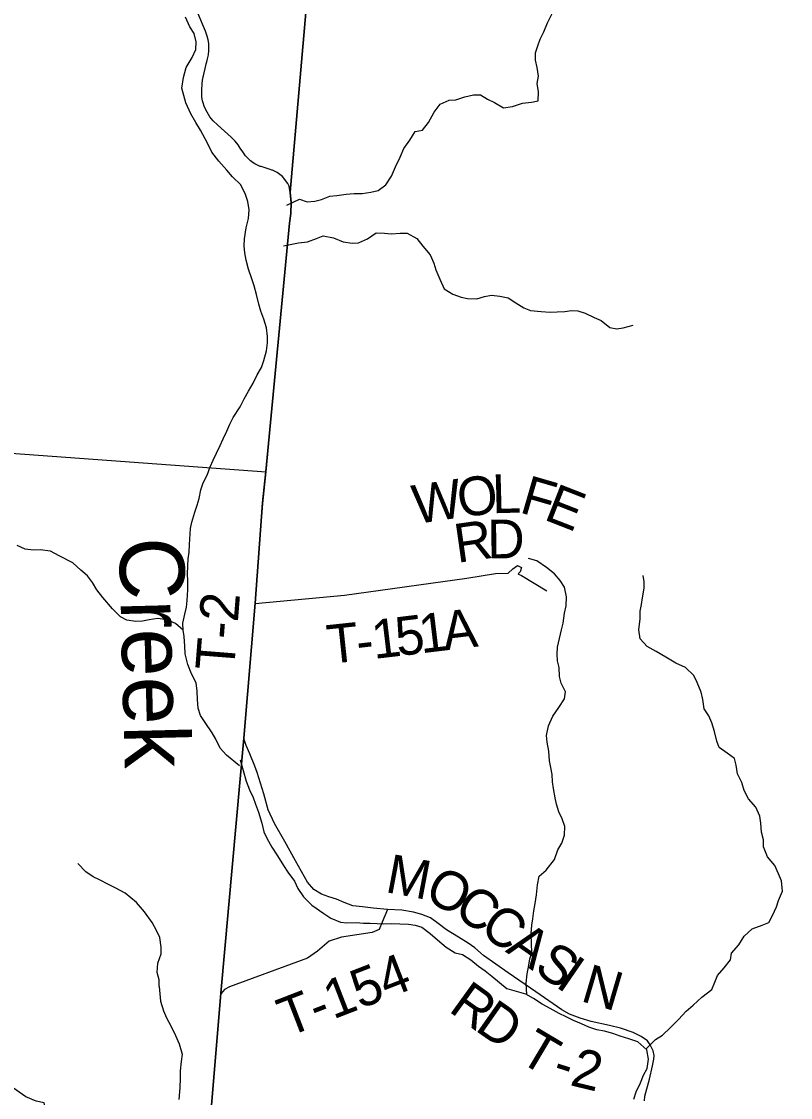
# Model space of a CAD drawing. Extents: x 0 to 42.5, y 0 to 22.
# Drawn here: x 8.111 to 8.674, y 16.629 to 17.417 of the extents above; entities that cross this region are included whole.
import ezdxf

# ---------------------------------------------------------------- set-up
doc = ezdxf.new("R2010")
doc.units = 0
for name, color, linetype in [('GM_X_Interchange_Ramps', 7, 'Continuous'), ('GM_X_Minor_River', 7, 'Continuous'), ('GM_X_Minor_River_Text', 7, 'Continuous'), ('GM_X_Township', 7, 'Continuous'), ('GM_X_Township_Road', 7, 'Continuous'), ('GM_X_Township_Road_Text', 7, 'Continuous'), ('SH_Cut_Line', 7, 'Continuous')]:
    doc.layers.add(name, color=color, linetype=linetype)

msp = doc.modelspace()

# ---------------------------------------------------------------- linework, layer by layer
at = {"layer": 'GM_X_Interchange_Ramps'}
msp.add_lwpolyline([(8.9, 15.53758), (8.9, 19.05381), (8.80207, 19.06082), (8.79715, 19.06117), (8.45529, 19.08562), (8.42249, 18.59682), (8.4216, 18.58362), (8.41233, 18.47844), (8.38323, 18.14846), (8.33786, 17.63394), (8.30797, 17.29222), (8.30866, 17.28459), (8.30841, 17.27648), (8.30737, 17.26941), (8.29023, 17.08765), (8.28773, 17.0646), (8.28228, 16.99116), (8.27401, 16.89234), (8.25723, 16.70556), (8.24802, 16.59431), (8.24781, 16.59008), (8.17933, 15.79111)], dxfattribs=at)
at = {"layer": 'GM_X_Minor_River'}
for p, q in [((8.4965, 17.4162), (8.50014, 17.42359)), ((8.49363, 17.40958), (8.4965, 17.4162)), ((8.49115, 17.40428), (8.49363, 17.40958)), ((8.48769, 17.39424), (8.48923, 17.39935)), ((8.48923, 17.39935), (8.49115, 17.40428)), ((8.48767, 17.38893), (8.48769, 17.39424)), ((8.48879, 17.38342), (8.48767, 17.38893)), ((8.4899, 17.37716), (8.48879, 17.38342)), ((8.48874, 17.37186), (8.4899, 17.37716)), ((8.48986, 17.36559), (8.48874, 17.37186)), ((8.41777, 17.35677), (8.42442, 17.35959)), ((8.42442, 17.35959), (8.42916, 17.35995)), ((8.42916, 17.35995), (8.4358, 17.36201)), ((8.4358, 17.36201), (8.44226, 17.3635)), ((8.44226, 17.3635), (8.44738, 17.36348)), ((8.44738, 17.36348), (8.45248, 17.36024)), ((8.45248, 17.36024), (8.45759, 17.35794)), ((8.47807, 17.35748), (8.48471, 17.35803)), ((8.48471, 17.35803), (8.48964, 17.35915)), ((8.48964, 17.35915), (8.48986, 17.36559)), ((8.40937, 17.34333), (8.41339, 17.35072)), ((8.41339, 17.35072), (8.41777, 17.35677)), ((8.45759, 17.35794), (8.46421, 17.35393)), ((8.46421, 17.35393), (8.47085, 17.35486)), ((8.47085, 17.35486), (8.47807, 17.35748)), ((8.4048, 17.33766), (8.40937, 17.34333)), ((8.39548, 17.3303), (8.39949, 17.33655)), ((8.39949, 17.33655), (8.4048, 17.33766)), ((8.39129, 17.32425), (8.39548, 17.3303)), ((8.38861, 17.31781), (8.39129, 17.32425)), ((8.38229, 17.30399), (8.38516, 17.31081)), ((8.38516, 17.31081), (8.38861, 17.31781)), ((8.3781, 17.29756), (8.38229, 17.30399)), ((8.37239, 17.29341), (8.3781, 17.29756)), ((8.33103, 17.28674), (8.33711, 17.28919)), ((8.33711, 17.28919), (8.34223, 17.28973)), ((8.34223, 17.28973), (8.34887, 17.29085)), ((8.34887, 17.29085), (8.35494, 17.2912)), ((8.35494, 17.2912), (8.36063, 17.29118)), ((8.36063, 17.29118), (8.36708, 17.2921)), ((8.36708, 17.2921), (8.37239, 17.29341)), ((8.30553, 17.28259), (8.31492, 17.287)), ((8.31492, 17.287), (8.32041, 17.28508)), ((8.32041, 17.28508), (8.3261, 17.28562)), ((8.3261, 17.28562), (8.33103, 17.28674)), ((8.31403, 17.25514), (8.32067, 17.25587)), ((8.32067, 17.25587), (8.32731, 17.25831)), ((8.32731, 17.25831), (8.33206, 17.26019)), ((8.33206, 17.26019), (8.33964, 17.25883)), ((8.33964, 17.25883), (8.34683, 17.25596)), ((8.34683, 17.25596), (8.35328, 17.2548)), ((8.35802, 17.25516), (8.36448, 17.25798)), ((8.36448, 17.25798), (8.37094, 17.26232)), ((8.37094, 17.26232), (8.37701, 17.2621)), ((8.37701, 17.2621), (8.38193, 17.2617)), ((8.38193, 17.2617), (8.38857, 17.26225)), ((8.38857, 17.26225), (8.39369, 17.26223)), ((8.39369, 17.26223), (8.40069, 17.25822)), ((8.40069, 17.25822), (8.40522, 17.2527)), ((8.30303, 17.25298), (8.31403, 17.25514)), ((8.35328, 17.2548), (8.35802, 17.25516)), ((8.40522, 17.2527), (8.4105, 17.24623)), ((8.4105, 17.24623), (8.41313, 17.24034)), ((8.41313, 17.24034), (8.41463, 17.23541)), ((8.41463, 17.23541), (8.41745, 17.22857)), ((8.41745, 17.22857), (8.42083, 17.22154)), ((8.42083, 17.22154), (8.42707, 17.21753)), ((8.42707, 17.21753), (8.43313, 17.21523)), ((8.4502, 17.21574), (8.45532, 17.21667)), ((8.45532, 17.21667), (8.46139, 17.21607)), ((8.43313, 17.21523), (8.43787, 17.21427)), ((8.43787, 17.21427), (8.44469, 17.21405)), ((8.44469, 17.21405), (8.4502, 17.21574)), ((8.46139, 17.21607), (8.46764, 17.21491)), ((8.46764, 17.21491), (8.47331, 17.21129)), ((8.47331, 17.21129), (8.47899, 17.20747)), ((8.47899, 17.20747), (8.48391, 17.20556)), ((8.48391, 17.20556), (8.49168, 17.20477)), ((8.49168, 17.20477), (8.49831, 17.20436)), ((8.49831, 17.20436), (8.50343, 17.20453)), ((8.50343, 17.20453), (8.50912, 17.20489)), ((8.50912, 17.20489), (8.51386, 17.20544)), ((8.51386, 17.20544), (8.5186, 17.20542)), ((8.5186, 17.20542), (8.52391, 17.20351)), ((8.52391, 17.20351), (8.53053, 17.20045)), ((8.53053, 17.20045), (8.53564, 17.19834)), ((8.53564, 17.19834), (8.54207, 17.1932)), ((8.54207, 17.1932), (8.54718, 17.19204)), ((8.54718, 17.19204), (8.55193, 17.19297)), ((8.55193, 17.19297), (8.55914, 17.19484)), ((8.48867, 17.02215), (8.48261, 17.02407)), ((8.49567, 17.01738), (8.48867, 17.02215)), ((8.50153, 17.01281), (8.49567, 17.01738)), ((8.50568, 17.00786), (8.50153, 17.01281)), ((8.5673, 17.00687), (8.56656, 17.01161)), ((8.50888, 17.00292), (8.50568, 17.00786)), ((8.56709, 17.00213), (8.5673, 17.00687)), ((8.51037, 16.9959), (8.50888, 17.00292)), ((8.50997, 16.98926), (8.51037, 16.9959)), ((8.56592, 16.99511), (8.56709, 17.00213)), ((8.50881, 16.98396), (8.50997, 16.98926)), ((8.56437, 16.98545), (8.56534, 16.99038)), ((8.56534, 16.99038), (8.56592, 16.99511)), ((8.50783, 16.97656), (8.50881, 16.98396)), ((8.56416, 16.97976), (8.56437, 16.98545)), ((8.50667, 16.97183), (8.50783, 16.97656)), ((8.56336, 16.97161), (8.56416, 16.97976)), ((8.50378, 16.95913), (8.50513, 16.96538)), ((8.50513, 16.96538), (8.50667, 16.97183)), ((8.56429, 16.96516), (8.56336, 16.97161)), ((8.56938, 16.95945), (8.56429, 16.96516)), ((8.50338, 16.95382), (8.50378, 16.95913)), ((8.576, 16.95582), (8.56938, 16.95945)), ((8.50374, 16.94908), (8.50338, 16.95382)), ((8.50486, 16.94414), (8.50374, 16.94908)), ((8.583, 16.95162), (8.576, 16.95582)), ((8.59038, 16.94723), (8.583, 16.95162)), ((8.50521, 16.93751), (8.50486, 16.94414)), ((8.59738, 16.94417), (8.59038, 16.94723)), ((8.60362, 16.93826), (8.59738, 16.94417)), ((8.50652, 16.93276), (8.50521, 16.93751)), ((8.50953, 16.9263), (8.50652, 16.93276)), ((8.60606, 16.93314), (8.60362, 16.93826)), ((8.60888, 16.92611), (8.60606, 16.93314)), ((8.50875, 16.92118), (8.50953, 16.9263)), ((8.61018, 16.9206), (8.60888, 16.92611)), ((8.50474, 16.91494), (8.50875, 16.92118)), ((8.6111, 16.91396), (8.61018, 16.9206)), ((8.50035, 16.90851), (8.50474, 16.91494)), ((8.6145, 16.90864), (8.6111, 16.91396)), ((8.49575, 16.8943), (8.4971, 16.90132)), ((8.4971, 16.90132), (8.50035, 16.90851)), ((8.61675, 16.90351), (8.6145, 16.90864)), ((8.61881, 16.89724), (8.61675, 16.90351)), ((8.49611, 16.88937), (8.49575, 16.8943)), ((8.6203, 16.89022), (8.61881, 16.89724)), ((8.49741, 16.88292), (8.49611, 16.88937)), ((8.62199, 16.88547), (8.6203, 16.89022)), ((8.62785, 16.88147), (8.62199, 16.88547)), ((8.49795, 16.8759), (8.49741, 16.88292)), ((8.63333, 16.87746), (8.62785, 16.88147)), ((8.63445, 16.87272), (8.63333, 16.87746)), ((8.27124, 16.87644), (8.27567, 16.86082)), ((8.49888, 16.87096), (8.49795, 16.8759)), ((8.4998, 16.86584), (8.49888, 16.87096)), ((8.63556, 16.86627), (8.63445, 16.87272)), ((8.50016, 16.86034), (8.4998, 16.86584)), ((8.63876, 16.85981), (8.63556, 16.86627)), ((8.27567, 16.86082), (8.2783, 16.85456)), ((8.2783, 16.85456), (8.28093, 16.84886)), ((8.5009, 16.85541), (8.50016, 16.86034)), ((8.50201, 16.84876), (8.5009, 16.85541)), ((8.64044, 16.85411), (8.63876, 16.85981)), ((8.64364, 16.84784), (8.64044, 16.85411)), ((8.28093, 16.84886), (8.28262, 16.84411)), ((8.50294, 16.84402), (8.50201, 16.84876)), ((8.64893, 16.84194), (8.64364, 16.84784)), ((8.28262, 16.84411), (8.28487, 16.83822)), ((8.28487, 16.83822), (8.28711, 16.83025)), ((8.50481, 16.83832), (8.50294, 16.84402)), ((8.50707, 16.83319), (8.50481, 16.83832)), ((8.65193, 16.83529), (8.64893, 16.84194)), ((8.28711, 16.83025), (8.28861, 16.82379)), ((8.50913, 16.82769), (8.50707, 16.83319)), ((8.65267, 16.83017), (8.65193, 16.83529)), ((8.65303, 16.82353), (8.65267, 16.83017)), ((8.28861, 16.82379), (8.29086, 16.81904)), ((8.50892, 16.82143), (8.50913, 16.82769)), ((8.65452, 16.81783), (8.65303, 16.82353)), ((8.29086, 16.81904), (8.29463, 16.81258)), ((8.50394, 16.81064), (8.507, 16.81556)), ((8.507, 16.81556), (8.50892, 16.82143)), ((8.6545, 16.81271), (8.65452, 16.81783)), ((8.29463, 16.81258), (8.29858, 16.80631)), ((8.50145, 16.80344), (8.50394, 16.81064)), ((8.6575, 16.8055), (8.6545, 16.81271)), ((8.29858, 16.80631), (8.30311, 16.79908)), ((8.30311, 16.79908), (8.30631, 16.79433)), ((8.49554, 16.79569), (8.50145, 16.80344)), ((8.66279, 16.79922), (8.6575, 16.8055)), ((8.66561, 16.79295), (8.66279, 16.79922)), ((8.30631, 16.79433), (8.31121, 16.78767)), ((8.48905, 16.7849), (8.49021, 16.79135)), ((8.49021, 16.79135), (8.49554, 16.79569)), ((8.66786, 16.78782), (8.66561, 16.79295)), ((8.31121, 16.78767), (8.31366, 16.78235)), ((8.48845, 16.7777), (8.48905, 16.7849)), ((8.6684, 16.78042), (8.66786, 16.78782)), ((8.31366, 16.78235), (8.3178, 16.77608)), ((8.3178, 16.77608), (8.32385, 16.76999)), ((8.48748, 16.77126), (8.48845, 16.7777)), ((8.66553, 16.7736), (8.6684, 16.78042)), ((8.32385, 16.76999), (8.33273, 16.76389)), ((8.48651, 16.76595), (8.48748, 16.77126)), ((8.66112, 16.76243), (8.66399, 16.76887)), ((8.66399, 16.76887), (8.66553, 16.7736)), ((8.33273, 16.76389), (8.33784, 16.76064)), ((8.33784, 16.76064), (8.34484, 16.75758)), ((8.48495, 16.75533), (8.48573, 16.76007)), ((8.48573, 16.76007), (8.48651, 16.76595)), ((8.65845, 16.75751), (8.66112, 16.76243)), ((8.34484, 16.75758), (8.34958, 16.75718)), ((8.34958, 16.75718), (8.35622, 16.75735)), ((8.35622, 16.75735), (8.36171, 16.75695)), ((8.36171, 16.75695), (8.36664, 16.75693)), ((8.36664, 16.75693), (8.37176, 16.75672)), ((8.37176, 16.75672), (8.3765, 16.75651)), ((8.3765, 16.75651), (8.382, 16.75668)), ((8.382, 16.75668), (8.38826, 16.75646)), ((8.38826, 16.75646), (8.3947, 16.75625)), ((8.3947, 16.75625), (8.39944, 16.75547)), ((8.39944, 16.75547), (8.40436, 16.75394)), ((8.40436, 16.75394), (8.41041, 16.74936)), ((8.48455, 16.74927), (8.48495, 16.75533)), ((8.6404, 16.74734), (8.6463, 16.75282)), ((8.6463, 16.75282), (8.65351, 16.75545)), ((8.65351, 16.75545), (8.65845, 16.75751)), ((8.41041, 16.74936), (8.41589, 16.7446)), ((8.41589, 16.7446), (8.42232, 16.73927)), ((8.48471, 16.74187), (8.48455, 16.74927)), ((8.63658, 16.7411), (8.6404, 16.74734)), ((8.42232, 16.73927), (8.42875, 16.73526)), ((8.48487, 16.73542), (8.48471, 16.74187)), ((8.63106, 16.73486), (8.63658, 16.7411)), ((8.42875, 16.73526), (8.43405, 16.73391)), ((8.43405, 16.73391), (8.44029, 16.73009)), ((8.44029, 16.73009), (8.44577, 16.72533)), ((8.48255, 16.72462), (8.48353, 16.73069)), ((8.48353, 16.73069), (8.48487, 16.73542)), ((8.62589, 16.72426), (8.63047, 16.73012)), ((8.63047, 16.73012), (8.63106, 16.73486)), ((8.44577, 16.72533), (8.45069, 16.7219)), ((8.45069, 16.7219), (8.4556, 16.71809)), ((8.48159, 16.71969), (8.48255, 16.72462)), ((8.62094, 16.71859), (8.62589, 16.72426)), ((8.4556, 16.71809), (8.46694, 16.70876)), ((8.4808, 16.71287), (8.48159, 16.71969)), ((8.48124, 16.70463), (8.4808, 16.71287)), ((8.61673, 16.70845), (8.61903, 16.71367)), ((8.61903, 16.71367), (8.62094, 16.71859)), ((8.48053, 16.70503), (8.46694, 16.70876)), ((8.48619, 16.70177), (8.48053, 16.70503)), ((8.60946, 16.70268), (8.61673, 16.70845)), ((8.4926, 16.69756), (8.48619, 16.70177)), ((8.49825, 16.6943), (8.4926, 16.69756)), ((8.59784, 16.69252), (8.60317, 16.69684)), ((8.60317, 16.69684), (8.60946, 16.70268)), ((8.50486, 16.69084), (8.49825, 16.6943)), ((8.50995, 16.68834), (8.50486, 16.69084)), ((8.51542, 16.68565), (8.50995, 16.68834)), ((8.5923, 16.68629), (8.59784, 16.69252)), ((8.52127, 16.68315), (8.51542, 16.68565)), ((8.52656, 16.68065), (8.52127, 16.68315)), ((8.53241, 16.67891), (8.52656, 16.68065)), ((8.58067, 16.67499), (8.58658, 16.68045)), ((8.58658, 16.68045), (8.5923, 16.68629)), ((8.53809, 16.67792), (8.53241, 16.67891)), ((8.54413, 16.67599), (8.53809, 16.67792)), ((8.54961, 16.67424), (8.54413, 16.67599)), ((8.55603, 16.67231), (8.54961, 16.67424)), ((8.57553, 16.67161), (8.58067, 16.67499)), ((8.56265, 16.66999), (8.55603, 16.67231)), ((8.56904, 16.66407), (8.56265, 16.66999)), ((8.56831, 16.66475), (8.57553, 16.67161)), ((8.57032, 16.65723), (8.56904, 16.66407)), ((8.56932, 16.65041), (8.57032, 16.65723)), ((8.56682, 16.6455), (8.56932, 16.65041)), ((8.56451, 16.64001), (8.56682, 16.6455)), ((8.5595, 16.62791), (8.56143, 16.63339)), ((8.56143, 16.63339), (8.56451, 16.64001))]:
    msp.add_line(p, q, dxfattribs=at)
for points in [[(8.27093, 16.87219), (8.26134, 16.88001), (8.25661, 16.88514), (8.25359, 16.8916), (8.25094, 16.89634), (8.24564, 16.90394), (8.24223, 16.90889), (8.24054, 16.91439), (8.24017, 16.92065), (8.2398, 16.92673), (8.23924, 16.9328), (8.23565, 16.93945), (8.233, 16.94628), (8.23112, 16.95426), (8.23075, 16.95976), (8.23039, 16.96678), (8.22964, 16.97153), (8.22927, 16.97665), (8.23079, 16.98329), (8.23194, 16.98841), (8.23252, 16.99316), (8.23291, 17.00112), (8.23293, 17.00776), (8.23274, 17.01251), (8.23294, 17.01858), (8.23333, 17.0237), (8.23391, 17.02864), (8.2343, 17.03414), (8.23508, 17.0459), (8.23604, 17.05064), (8.23814, 17.05785), (8.23985, 17.06297), (8.24138, 17.0679), (8.24253, 17.07435), (8.24425, 17.07928), (8.24729, 17.08497), (8.24939, 17.09103), (8.25168, 17.09596), (8.25396, 17.10108), (8.25663, 17.10658), (8.25891, 17.11151), (8.26158, 17.1172), (8.26368, 17.12231), (8.26615, 17.12724), (8.27129, 17.13501), (8.27433, 17.14089), (8.27738, 17.14639), (8.2808, 17.15245), (8.28385, 17.15833), (8.28708, 17.16382), (8.28861, 17.16894), (8.29052, 17.17596), (8.29148, 17.18184), (8.2913, 17.18659), (8.29055, 17.19285), (8.28867, 17.1993), (8.28659, 17.20519), (8.28508, 17.21013), (8.2832, 17.21734), (8.28169, 17.22361), (8.2798, 17.22873), (8.27754, 17.23576), (8.27565, 17.2424), (8.27471, 17.24772), (8.27416, 17.25303), (8.27454, 17.25816), (8.2757, 17.26612), (8.27742, 17.27295), (8.278, 17.2794), (8.27687, 17.28529), (8.27536, 17.2906), (8.27177, 17.29763), (8.26571, 17.30352), (8.26154, 17.30828), (8.25567, 17.31493), (8.25056, 17.32139), (8.2483, 17.32614), (8.24565, 17.33127), (8.24225, 17.33754), (8.23884, 17.34324), (8.23525, 17.34969), (8.23166, 17.35767), (8.22864, 17.3683), (8.22979, 17.37627), (8.23189, 17.38348), (8.23627, 17.39087), (8.23894, 17.39675), (8.23914, 17.40225), (8.23763, 17.40832), (8.23441, 17.41326), (8.23139, 17.42029)], [(8.22964, 16.97153), (8.22395, 16.97628), (8.21789, 16.97914), (8.21106, 16.97991), (8.20461, 16.97898), (8.19986, 16.97804), (8.19493, 16.97786), (8.18848, 16.97882), (8.18374, 16.9813), (8.17787, 16.987), (8.17087, 16.99536), (8.16651, 17.00106), (8.16311, 17.00638), (8.15951, 17.01114), (8.15478, 17.01532), (8.14872, 17.02083), (8.13886, 17.02579), (8.13242, 17.02921), (8.12483, 17.03037), (8.12009, 17.03), (8.11402, 17.03077), (8.10795, 17.03344)], [(8.21209, 16.71046), (8.2121, 16.7154), (8.21059, 16.72071), (8.21117, 16.72773), (8.21346, 16.73437), (8.21347, 16.7393), (8.21253, 16.74652), (8.21008, 16.75164), (8.20686, 16.75734), (8.20138, 16.76532), (8.19532, 16.77198), (8.18717, 16.77882), (8.18035, 16.78244), (8.17485, 16.78511), (8.16841, 16.78854), (8.16367, 16.79082), (8.15836, 16.79444), (8.15249, 16.80052)], [(8.21209, 16.71046), (8.21295, 16.69987), (8.21517, 16.69264), (8.21741, 16.68751), (8.22078, 16.68122), (8.22396, 16.67475), (8.22657, 16.66866), (8.22879, 16.66105), (8.22818, 16.65555), (8.22738, 16.64873), (8.22734, 16.64341), (8.2271, 16.63639), (8.22648, 16.62786)], [(8.11071, 16.57261), (8.11623, 16.57656), (8.1214, 16.58317), (8.12427, 16.58808), (8.12621, 16.59396), (8.12757, 16.59983), (8.12875, 16.60627), (8.12959, 16.6169), (8.12794, 16.62545), (8.12188, 16.62662), (8.11433, 16.62971), (8.10282, 16.63775)]]:
    msp.add_lwpolyline(points, dxfattribs=at)
at = {"layer": 'GM_X_Township'}
msp.add_lwpolyline([(8.33786, 17.63394), (8.30797, 17.29222), (8.30866, 17.28459), (8.30841, 17.27648), (8.30737, 17.26941), (8.29023, 17.08765), (8.28773, 17.0646), (8.28228, 16.99116), (8.27401, 16.89234), (8.25723, 16.70556), (8.24802, 16.59431), (8.24781, 16.59008), (8.17933, 15.79111)], dxfattribs=at)
at = {"layer": 'GM_X_Township_Road'}
for p, q in [((7.44962, 17.14878), (8.29034, 17.08739)), ((8.27412, 16.89208), (8.28239, 16.9909))]:
    msp.add_line(p, q, dxfattribs=at)
for points in [[(8.30808, 17.29196), (8.3072, 17.29658), (8.30617, 17.29846), (8.30237, 17.30364), (8.29839, 17.30659), (8.29646, 17.3076), (8.29504, 17.30821), (8.29446, 17.30843), (8.29333, 17.30891), (8.29045, 17.3097), (8.28665, 17.31095), (8.28607, 17.31112), (8.28409, 17.31196), (8.28219, 17.31295), (8.28091, 17.31377), (8.27899, 17.31526), (8.27718, 17.31689), (8.27531, 17.31893), (8.27332, 17.32167), (8.27143, 17.32451), (8.26984, 17.32681), (8.26771, 17.32947), (8.26468, 17.33258), (8.25983, 17.33694), (8.25472, 17.34147), (8.25163, 17.34451), (8.24923, 17.34734), (8.24806, 17.34917), (8.24629, 17.35244), (8.24508, 17.3553), (8.24423, 17.35763), (8.24384, 17.35913), (8.24339, 17.36188), (8.24328, 17.36435), (8.24335, 17.36714), (8.24358, 17.37149), (8.24384, 17.37427), (8.24425, 17.37674), (8.24443, 17.37734), (8.24625, 17.38488), (8.24651, 17.38609), (8.24673, 17.38698), (8.24699, 17.38777), (8.24748, 17.3898), (8.24805, 17.39282), (8.2484, 17.39592), (8.24849, 17.39871), (8.24833, 17.40119), (8.24795, 17.40365), (8.24725, 17.40636), (8.24591, 17.41017), (8.24381, 17.41535), (8.24013, 17.42392)], [(8.29034, 17.08739), (8.30748, 17.26915), (8.30852, 17.27621), (8.30877, 17.28432), (8.30808, 17.29196)], [(8.28239, 16.9909), (8.28784, 17.06434), (8.29034, 17.08739)], [(8.28239, 16.9909), (8.34782, 16.99718), (8.43741, 17.00953), (8.45838, 17.01299), (8.46772, 17.01322), (8.471, 17.01649), (8.47455, 17.01876), (8.47726, 17.01734), (8.4764, 17.01421), (8.47484, 17.01279), (8.47524, 17.01256)], [(8.47524, 17.01256), (8.47727, 17.01144), (8.49599, 17.00017)], [(8.56734, 16.62681), (8.56777, 16.63011), (8.57107, 16.64275), (8.57323, 16.65238), (8.57423, 16.65726), (8.57452, 16.65999), (8.57366, 16.66344), (8.57165, 16.6679), (8.56963, 16.67062), (8.56489, 16.67393), (8.55915, 16.67695), (8.54981, 16.68011), (8.54176, 16.68197), (8.5284, 16.68499), (8.52021, 16.68729), (8.5126, 16.69031), (8.507, 16.69347), (8.48775, 16.70668), (8.46763, 16.72062), (8.44953, 16.73312), (8.44321, 16.73887), (8.43833, 16.74217), (8.43129, 16.74677), (8.42238, 16.75194), (8.41635, 16.75668), (8.41074, 16.7607), (8.40428, 16.76329), (8.39824, 16.76487), (8.38962, 16.76645), (8.37914, 16.76688), (8.36874, 16.76798), (8.36087, 16.76881), (8.35393, 16.76954), (8.34753, 16.77205), (8.34193, 16.77449), (8.33633, 16.77607), (8.33101, 16.77823), (8.32526, 16.78153), (8.32067, 16.78699), (8.31636, 16.79475), (8.31176, 16.80265), (8.304, 16.81673), (8.29639, 16.8298), (8.29193, 16.84), (8.28863, 16.8515), (8.28374, 16.86716), (8.28202, 16.8719), (8.27843, 16.8808), (8.27584, 16.88698), (8.27412, 16.89208)], [(8.37914, 16.76688), (8.37543, 16.75766), (8.37308, 16.75218), (8.36811, 16.74996), (8.34544, 16.74662), (8.33647, 16.74369), (8.32802, 16.73638), (8.32054, 16.73134), (8.26352, 16.71034), (8.25986, 16.70823), (8.25734, 16.7053)], [(8.24792, 16.58982), (8.24813, 16.59404), (8.25734, 16.7053)]]:
    msp.add_lwpolyline(points, dxfattribs=at)
at = {"layer": 'SH_Cut_Line'}
for points in [[(8.9, 14.1), (8.9, 19.05381), (8.80207, 19.06082), (8.79715, 19.06117), (8.45529, 19.08562), (8.42249, 18.59682), (8.4216, 18.58362), (8.41233, 18.47844), (8.38323, 18.14846), (8.33786, 17.63394), (8.30797, 17.29222), (8.30866, 17.28459), (8.30841, 17.27648), (8.30737, 17.26941), (8.29023, 17.08765), (8.28773, 17.0646), (8.28228, 16.99116), (8.27401, 16.89234), (8.25723, 16.70556), (8.24802, 16.59431), (8.24781, 16.59008), (8.17933, 15.79111)], [(8.17933, 15.79111), (8.24781, 16.59008), (8.24802, 16.59431), (8.25723, 16.70556), (8.27401, 16.89234), (8.28228, 16.99116), (8.28773, 17.0646), (8.29023, 17.08765), (8.30737, 17.26941), (8.30841, 17.27648), (8.30866, 17.28459), (8.30797, 17.29222), (8.33786, 17.63394)]]:
    msp.add_lwpolyline(points, dxfattribs=at)

# ---------------------------------------------------------------- texts
at = {"layer": 'GM_X_Minor_River_Text'}
msp.add_text('Creek', height=0.047349, rotation=271.44743, dxfattribs=at).set_placement((8.18264, 17.03894))
at = {"layer": 'GM_X_Township_Road_Text'}
for s, height, rotation, p in [('W', 0.02841, 8.44116, (8.39971, 17.0491)), ('O', 0.02841, 7.3455, (8.43212, 17.05392)), ('L', 0.02841, 1.53866, (8.45616, 17.05705)), ('F', 0.02841, 343.7818, (8.4751, 17.05792)), ('E', 0.02841, 338.65142, (8.49287, 17.05278)), ('R', 0.02841, 8.12182, (8.43026, 17.02069)), ('D', 0.02841, 0.74316, (8.4524, 17.02391)), ('T-2', 0.028409, 85.44517, (8.26678, 16.94113)), ('1', 0.02841, 6.78178, (8.36934, 16.95034)), ('5', 0.02841, 6.87381, (8.38663, 16.95239)), ('1', 0.02841, 6.90289, (8.40388, 16.95448)), ('A', 0.02841, 6.90862, (8.42112, 16.95656)), ('T', 0.02841, 6.08655, (8.33639, 16.94672)), ('-', 0.02841, 6.60876, (8.35776, 16.949)), ('M', 0.02841, 349.29888, (8.37681, 16.77983)), ('O', 0.02841, 332.53565, (8.40504, 16.77482)), ('C', 0.02841, 325.73512, (8.42646, 16.76375)), ('C', 0.02841, 323.29715, (8.44548, 16.75079)), ('A', 0.02841, 325.12389, (8.46499, 16.73627)), ('S', 0.02841, 325.1896, (8.48553, 16.72195)), ('T-154', 0.028409, 21.17637, (8.30598, 16.67333)), ('I', 0.02841, 325.44626, (8.50138, 16.71093)), ('N', 0.02841, 343.54342, (8.5198, 16.70011)), ('R', 0.02841, 324.23864, (8.42318, 16.69285)), ('D', 0.02841, 325.0136, (8.44245, 16.67898)), ('T', 0.02841, 329.23395, (8.47415, 16.65637)), ('2', 0.02841, 346.44111, (8.51209, 16.63842)), ('-', 0.02841, 342.11256, (8.49874, 16.64264))]:
    msp.add_text(s, height=height, rotation=rotation, dxfattribs=at).set_placement(p)

doc.saveas('drawing.dxf')
